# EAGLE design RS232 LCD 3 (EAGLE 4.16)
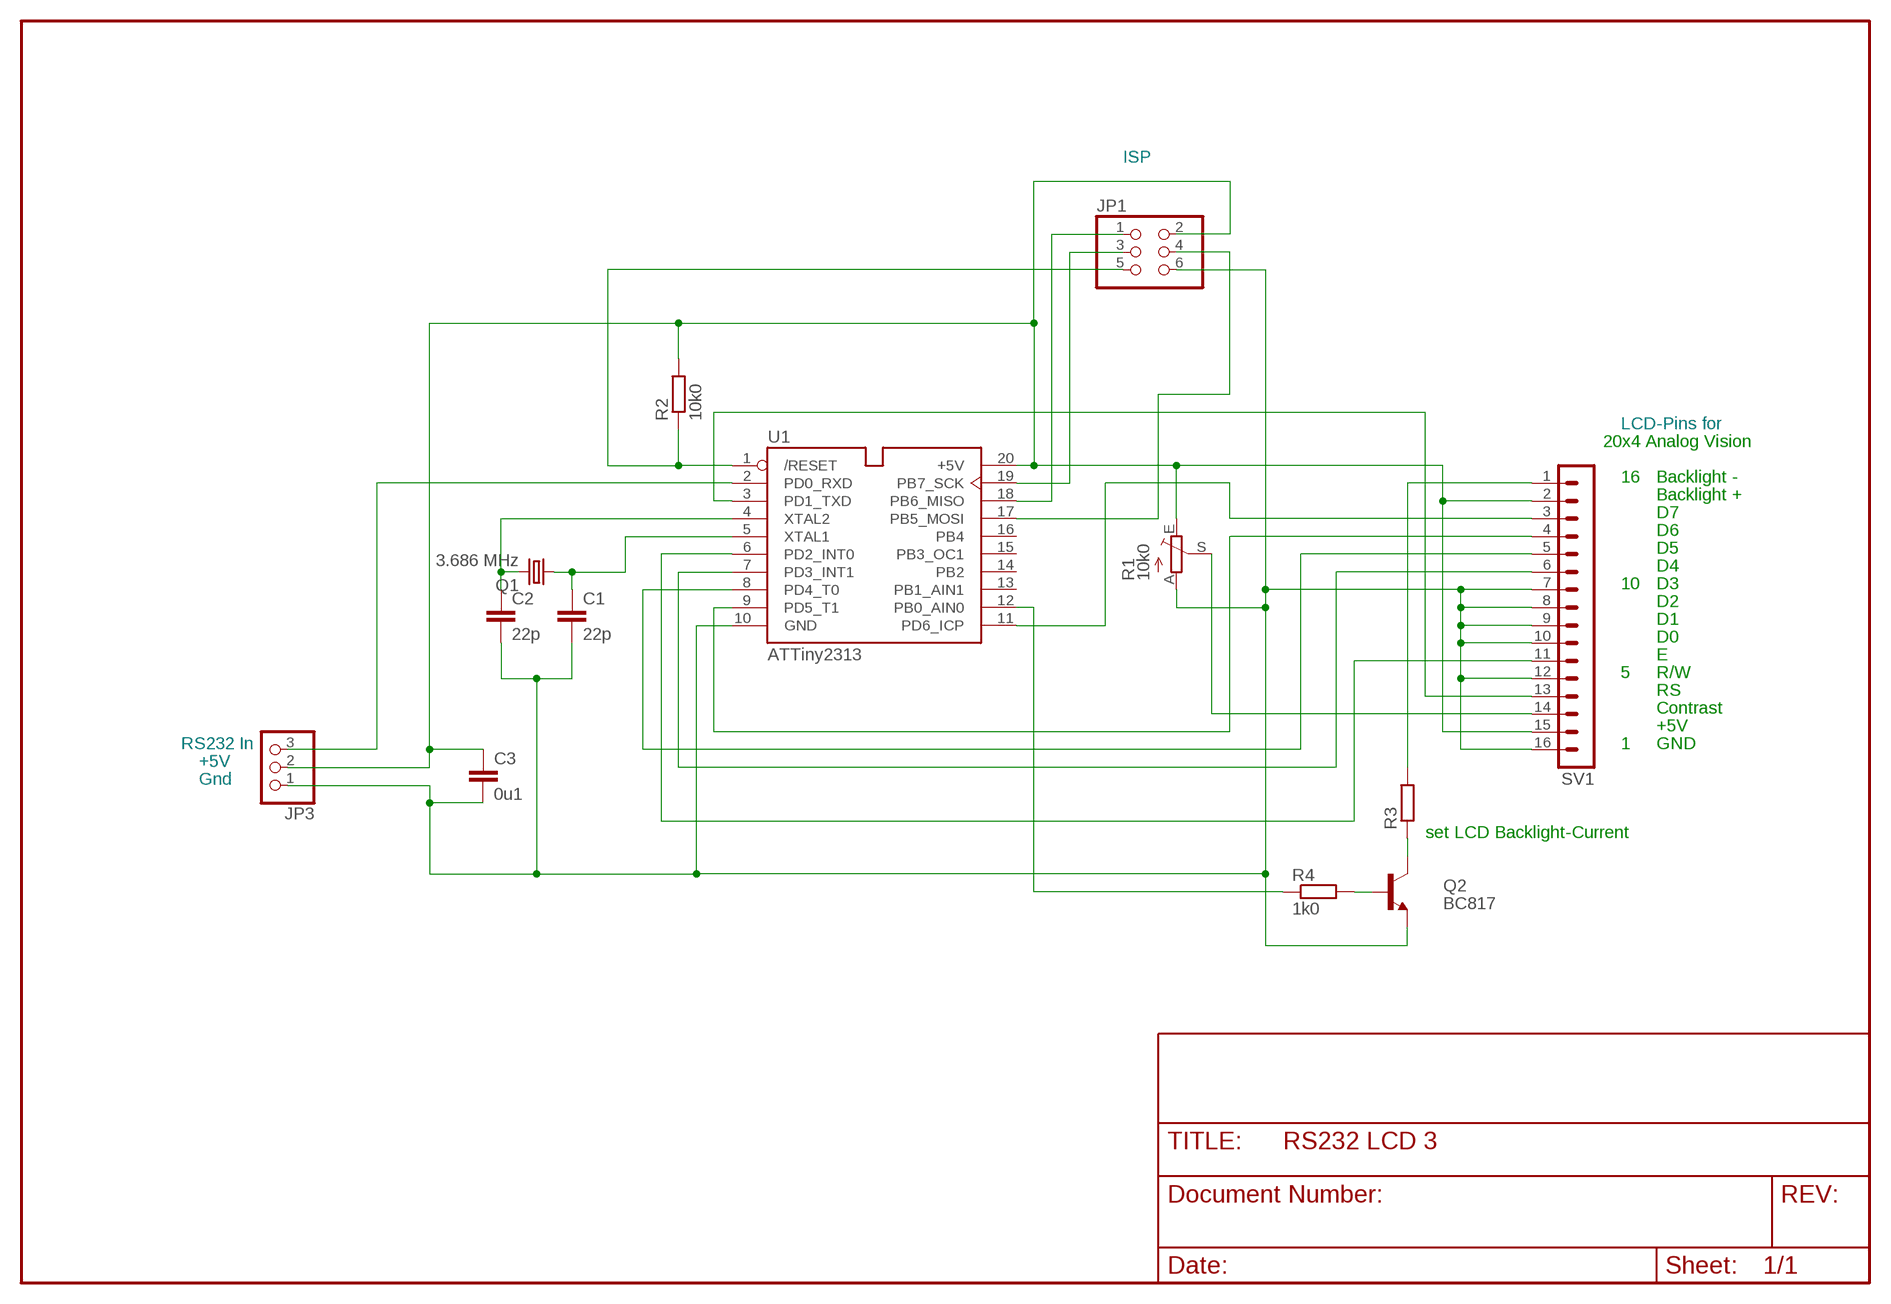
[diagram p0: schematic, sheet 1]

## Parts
C1  22p  C-EU050-025X075  [C050-025X075]
C2  22p  C-EU050-025X075  [C050-025X075]
C3  0u1  C-EU025-030X050  [C025-030X050]
JP1  PINHD-2X3  [2X03]
JP3  PINHD-1X3  [1X03]
Q1  3.686 MHz  CRYSTALHC18U-V  [HC18U-V]
Q2  BC817  BC817-16LT1SMD  [SOT23-BEC]
R1  10k0  TRIM_EU-PT10  [PT-10]
R2  10k0  R-EU_0207/10  [0207/10]
R3  R-EU_0207/10  [0207/10]
R4  1k0  R-EU_0207/10  [0207/10]
SV1  MA16-1  [MA16-1]
U1  ATTiny2313  AT90S2313_SO-20  [SO-20]

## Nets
+5V [Power]: C3.1 JP1.2 JP3.2 R1.E R2.2 SV1.2 SV1.15 U1.20(+5V)
BL- [Power]: R3.2 SV1.1
BL_BASE: Q2.B R4.2
BL_COLLECTOR [Power]: Q2.C R3.1
BL_CONTROL: R4.1 U1.12(PB0_AIN0)
CONTR: R1.S SV1.14
D4: SV1.6 U1.7(PD3_INT1)
D5: SV1.5 U1.8(PD4_T0)
D6: SV1.4 U1.9(PD5_T1)
D7: SV1.3 U1.11(PD6_ICP)
E: SV1.11 U1.6(PD2_INT0)
GND [Power]: C1.2 C2.2 C3.2 JP1.6 JP3.1 Q2.E R1.A SV1.7 SV1.8 SV1.9 SV1.10 SV1.12 SV1.16 U1.10(GND)
MISO: JP1.1 U1.18(PB6_MISO)
MOSI: JP1.4 U1.17(PB5_MOSI)
R/S: SV1.13 U1.3(PD1_TXD)
RST: JP1.5 R2.1 U1.1(/RESET)
RXD: JP3.3 U1.2(PD0_RXD)
SCK: JP1.3 U1.19(PB7_SCK)
XTAL1: C1.1 Q1.1 U1.5(XTAL1)
XTAL2: C2.1 Q1.2 U1.4(XTAL2)
Unconnected: U1.13(PB1_AIN1) U1.14(PB2) U1.15(PB3_OC1) U1.16(PB4)

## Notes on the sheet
- ISP
- LCD-Pins for
- 20x4 Analog Vision
- 16 | Backlight -
- Backlight +
- D7
- D6
- D5
- D4
- 10 | D3
- D2
- D1
- D0
- E
- 5 | R/W
- RS
- Contrast
- +5V
- RS232 In | 1 | GND
- +5V
- Gnd
- set LCD Backlight-Current

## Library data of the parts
C1-C3 = rcl:C-EU: CAPACITOR, European symbol
JP1 = pinhead:PINHD-2X3: PIN HEADER
JP3 = pinhead:PINHD-1X3: PIN HEADER
Q1 = crystal:CRYSTAL: CRYSTAL
Q2 = transistor-npn:BC817*: NPN Transistor
R1 = pot:TRIM_EU-: POTENTIOMETER
R2-R4 = rcl:R-EU_: RESISTOR, European symbol
SV1 = con-lstb:MA16-1
U1 = atmel_prototype_header:AT90S2313: 8-bit AVR Microcontroller with 2K bytes In-System Programmable Flash

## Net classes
0 default: width 0.254 mm
1 Power: width 0.61 mm

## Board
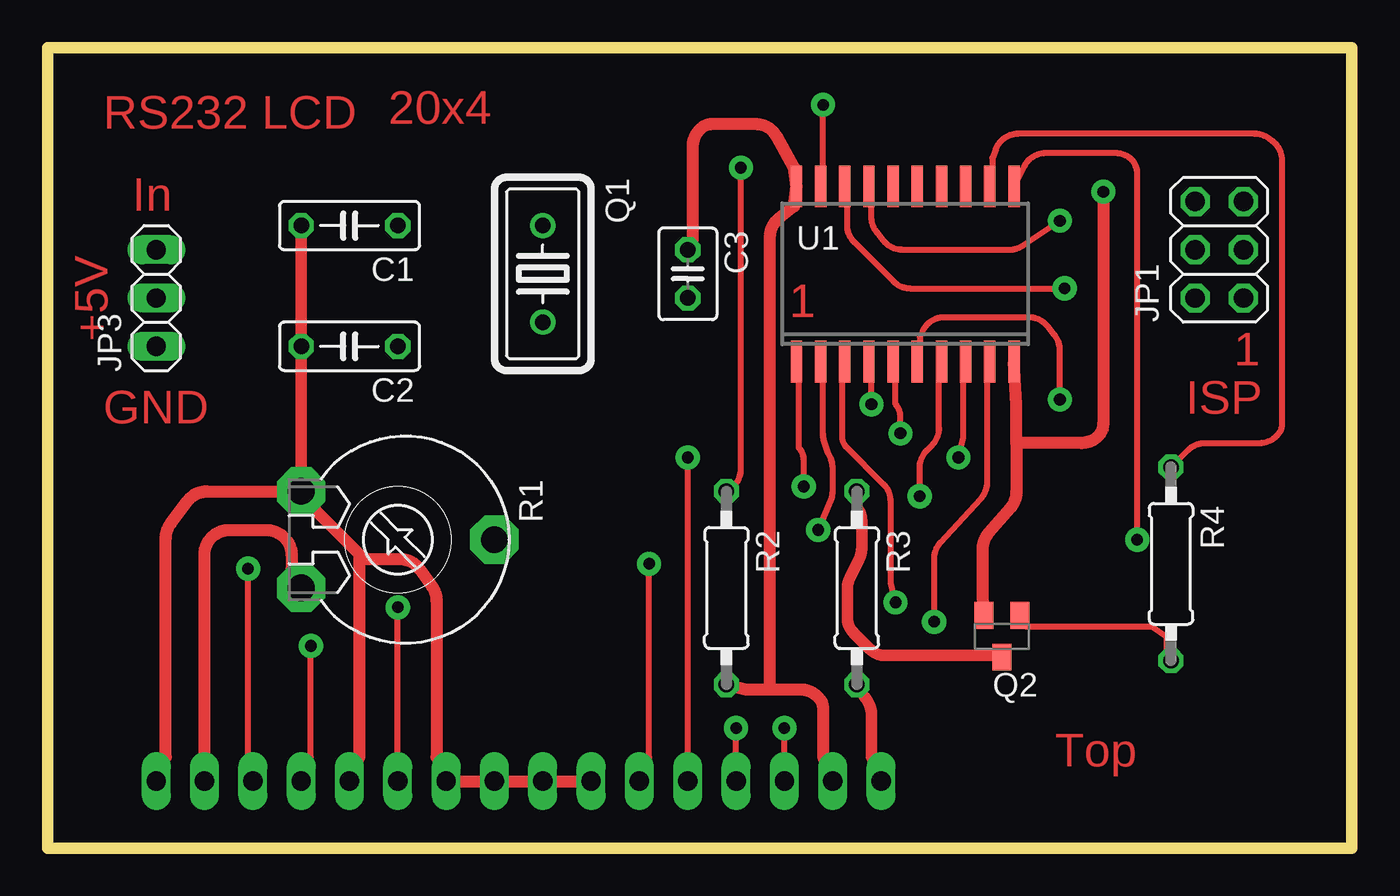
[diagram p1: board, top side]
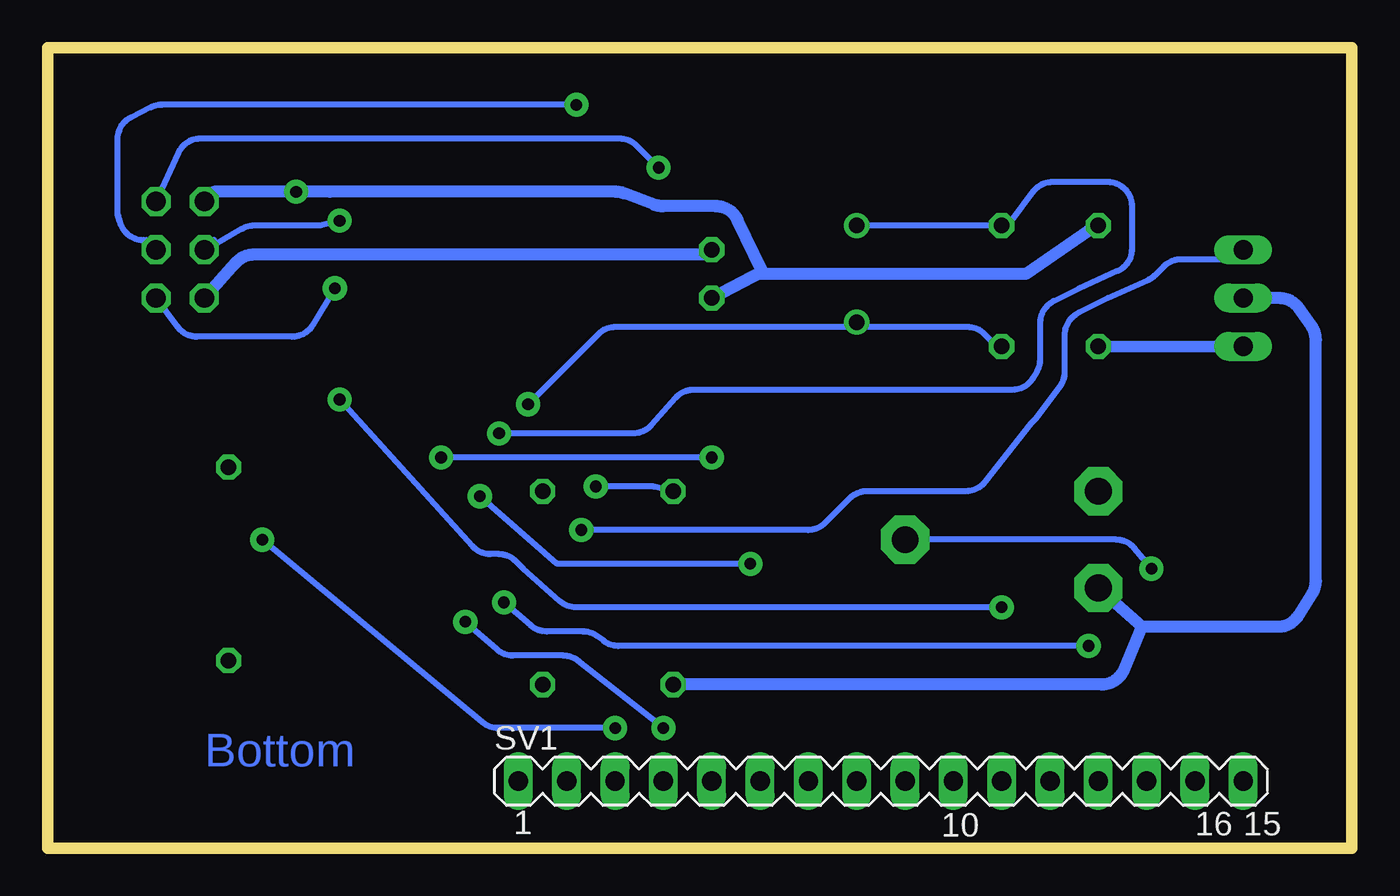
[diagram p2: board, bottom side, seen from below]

Size 68.56 x 42.09 mm. Coordinates in mm from the lower left corner, seen from the top.
Outline: 0,0 68.56,0 68.56,42.09 0,42.09 0,0
Copper layers (1*16): Top 0.035mm / dielectric 1.5mm / Bottom 0.035mm
Design rules "Doppelt_eigene_grosse_vias": minimum track width 12mil, minimum drill 24mil, track to track 15mil, track to pad 15mil, pad to pad 20mil, via to via 20mil, smd to smd 8mil, copper to edge 20mil, drill to drill 8mil, minimum pad ring 10mil, minimum via ring 13mil, stop-mask expansion 4mil, vias tented up to drill 0mil, thermal gap 10mil
tRestrict: area 59.1,27.6 to 64.1,35.3; area 24.8,26.4 to 27.3,34; area 4.4,25.1 to 7,32.7; area 4.4,-0.3 to 43.8,2.2
bRestrict: area 4.4,2.2 to 45.1,4.8
vRestrict: area 38.7,27.6 to 51.4,32.7

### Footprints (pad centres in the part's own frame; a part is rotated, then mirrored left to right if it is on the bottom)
C050-025X075 = drill 0.813 octagon: 1 -2.54,0; 2 2.54,0
C025-030X050 = drill 0.813 octagon: 1 -1.27,0; 2 1.27,0
2X03 = drill 1.016 octagon: 1 -2.54,-1.27; 2 -2.54,1.27; 3 0,-1.27; 4 0,1.27; 5 2.54,-1.27; 6 2.54,1.27
1X03 = drill 1.016 long: 1 -2.54,0; 2 0,0; 3 2.54,0
HC18U-V = drill 0.813 round: 1 -2.54,0; 2 2.54,0
SOT23-BEC = smd 1 x 1.4: B -0.95,-1.1; C 0,1.1; E 0.95,-1.1
PT-10 = drill 1.4 pad 2.54 octagon: A -2.54,-5.08; E 2.54,-5.08; S 0,5.08
0207/10 = drill 0.813 octagon: 1 -5.08,0; 2 5.08,0
MA16-1 = drill 1.016 long: 1 -19.05,0; 2 -16.51,0; 3 -13.97,0; 4 -11.43,0; 5 -8.89,0; 6 -6.35,0; 7 -3.81,0; 8 -1.27,0; 9 1.27,0; 10 3.81,0; 11 6.35,0; 12 8.89,0; 13 11.43,0; 14 13.97,0; 15 16.51,0; 16 19.05,0
SO-20 = smd 0.6 x 2.2: 1 -5.715,-4.6; 2 -4.445,-4.6; 3 -3.175,-4.6; 4 -1.905,-4.6; 5 -0.635,-4.6; 6 0.635,-4.6; 7 1.905,-4.6; 8 3.175,-4.6; 9 4.445,-4.6; 10 5.715,-4.6; 11 5.715,4.6; 12 4.445,4.6; 13 3.175,4.6; 14 1.905,4.6; 15 0.635,4.6; 16 -0.635,4.6; 17 -1.905,4.6; 18 -3.175,4.6; 19 -4.445,4.6; 20 -5.715,4.6

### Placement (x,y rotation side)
C1  15.87,32.73 180 top
C2  15.87,26.38 180 top
C3  33.65,30.19 270 top
JP1  61.59,31.46 90 top
JP3  5.71,28.92 90 top
Q1  26.03,30.19 270 top
Q2  50.16,11.14 180 top
R1  18.41,16.22 270 top
R2  35.68,13.68 270 top
R3  42.54,13.68 270 top
R4  59.05,14.95 270 top
SV1  24.76,3.52 0 bottom
U1  45.08,30.19 0 top

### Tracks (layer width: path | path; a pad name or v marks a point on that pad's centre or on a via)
+5V
  Top 0.635: SV1.15 8.25,15.44 arc-45 8.62,16.34 8.64,16.35 arc-45 9.54,16.73 11.51,16.73 arc-27 12.07,16.59 12.12,16.57 arc-63 12.82,15.43 12.82,14.69 R1.E | 37.97,8.34 39.57,8.34 arc-56 40.63,7.78 arc-34 40.76,7.35 40.76,4.79 SV1.2 | 37.97,8.34 36.7,8.34 R2.2 | C3.1 33.9,31.97 33.9,36.87 arc-56 34.47,37.93 arc-34 34.9,38.06 37.22,38.06 arc-61 38.33,37.41 39.24,35.78 U1.20 39.24,33.74 38.45,33.11 arc51 37.97,32.12 37.97,8.34
  Bottom 0.635: JP3.2 3.82,28.92 arc54 2.79,28.39 2.14,27.47 arc36 1.9,26.73 1.9,14.04 arc32 2.09,13.37 2.8,12.24 arc58 3.87,11.65 11.04,11.65 | JP1.2 58.67,30.78 arc48 57.72,31.2 33.9,31.2 C3.1 | R1.E 11.04,11.65 | 11.04,11.65 11.99,9.38 arc67 13.16,8.6 R2.2
BL-
  Top 0.305: 42.93,7.95 42.79,8.09 R3.2
  Top 0.61: 42.93,7.95 arc-45 43.3,7.06 43.3,4.79 SV1.1
BL_BASE
  Top 0.305: Q2.B 51.43,11.65 58.03,11.65 58.8,11.14 58.8,10.38 R4.2
BL_COLLECTOR
  Top 0.305: 42.66,17.76 42.54,18 | 49.91,10.12 Q2.C
  Top 0.61: 49.91,10.12 44.08,10.12 arc-45 43.18,10.49 42.4,11.27 arc-45 42.03,12.17 42.03,13.63 arc-27 42.17,14.2 42.66,15.19 arc27 42.79,15.76 42.79,17.19 arc27 42.66,17.76 | 42.54,18 R3.1
BL_CONTROL
  Top 0.305: U1.12 49.65,35.78 49.65,36.28 49.84,36.76 arc-68 51.02,37.55 63.45,37.55 arc-37 64.22,37.3 64.38,37.17 arc-53 64.89,36.16 64.89,22.3 arc-34 64.76,21.86 arc-56 63.7,21.3 60.85,21.3 arc45 59.95,20.93 R4.1
CONTR  (via drill 0.61)
  Top 0.305: v10.54,14.69 10.54,5.04 SV1.14
  Bottom 0.305: v10.54,14.69 11.42,15.76 arc-50 12.4,16.22 R1.S
D4  (via drill 0.61)
  Top 0.305: v45.84,18.5 45.84,20.01 arc-45 46.21,20.91 46.49,21.18 arc45 46.86,22.08 46.86,24.6 U1.7 | v31.62,14.95 31.62,4.79 SV1.6
  Bottom 0.305: v45.84,18.5 41.78,14.95 v31.62,14.95
D5  (via drill 0.61)
  Top 0.305: v47.87,20.54 48.13,21.55 48.13,24.6 U1.8 | SV1.5 v33.65,20.54
  Bottom 0.305: v33.65,20.54 v47.87,20.54
D6  (via drill 0.61)
  Top 0.305: v46.6,11.9 46.6,15.22 arc-43 46.94,16.07 49.06,18.39 arc43 49.4,19.25 49.4,24.6 U1.9 | SV1.4 v36.19,6.31
  Bottom 0.305: v46.6,11.9 44.93,10.44 arc-41 44.1,10.12 41.46,10.12 arc38 40.67,9.85 v36.19,6.31
D7  (via drill 0.61)
  Top 0.305: v57.27,16.22 57.27,35.5 arc56 56.83,36.33 arc34 56.12,36.54 52.46,36.54 arc63 51.33,35.84 U1.11 | SV1.3 v38.73,6.31
  Bottom 0.305: v38.73,6.31 44.88,6.31 arc40 45.69,6.61 v57.27,16.22
E  (via drill 0.61)
  Top 0.305: v53.21,23.58 53.21,26.19 arc39 52.93,26.98 52.57,27.43 arc51 51.58,27.9 47.13,27.9 arc63 46,27.2 45.84,26.89 45.84,26.63 U1.6 | SV1.11 v18.41,12.66
  Bottom 0.305: v53.21,23.58 46.22,15.87 arc-48 45.28,15.46 44.84,15.46 arc45 43.95,15.08 43.56,14.69 41.63,12.98 arc-42 40.79,12.66 v18.41,12.66
GND  (via drill 0.61)
  Top 0.61: C1.2 C2.2 R1.A
  Top 0.635: SV1.7 SV1.8 SV1.9 SV1.10 20.44,4.79 20.44,13.02 arc36 20.21,13.76 19.55,14.67 arc54 18.52,15.2 16.38,15.2 | SV1.16 6.22,4.79 6.22,16.3 arc-37 6.47,17.07 7.36,18.25 arc-53 8.38,18.76 R1.A 14.09,17.74 16.38,15.46 16.38,15.2 | 16.38,15.2 16.38,4.79 SV1.12 | 50.92,21.3 50.92,23.33 U1.10 | 50.92,21.3 50.92,18.73 arc-41 50.61,17.89 49.46,16.58 arc41 49.14,15.74 49.14,13.17 Q2.E | v55.49,34.51 55.49,22.34 arc-56 55.05,21.51 arc-34 54.35,21.3 50.92,21.3
  Bottom 0.61: C2.2 JP3.1
  Bottom 0.635: 30.98,30.32 31.11,30.19 17.14,30.19 13.84,32.47 C1.2 | 30.98,30.32 33.14,29.17 C3.2 | 53.72,34.51 59.81,34.51 JP1.6 | 30.98,30.32 32.29,33.02 arc-64 33.43,33.74 36.21,33.74 arc21 36.66,33.83 38.26,34.43 arc-21 38.71,34.51 53.72,34.51 | 53.72,34.51 v55.49,34.51
MISO  (via drill 0.61)
  Top 0.305: v53.46,29.43 45.35,29.43 arc-45 44.45,29.8 42.4,31.85 arc-45 42.03,32.75 42.03,33.74 U1.18
  Bottom 0.305: v53.46,29.43 54.62,27.5 arc59 55.71,26.89 60.7,26.89 arc53 61.72,27.39 JP1.1
MOSI  (via drill 0.61)
  Top 0.305: v53.21,32.98 51.24,31.67 arc-34 50.54,31.46 44.93,31.46 arc-51 43.94,31.94 43.58,32.38 arc-39 43.3,33.17 43.3,33.74 U1.17
  Bottom 0.305: v53.21,32.98 54.22,32.73 57.7,32.73 arc-30 58.33,32.56 59.81,31.71 59.81,31.97 JP1.4
R/S  (via drill 0.61)
  Top 0.305: v44.57,12.92 44.32,13.93 44.32,18.23 arc45 43.95,19.13 41.96,21.11 arc-45 41.78,21.56 41.78,24.6 U1.3 | v13.84,10.63 13.84,4.79 SV1.13
  Bottom 0.305: v13.84,10.63 38.56,10.63 arc37 39.32,10.88 39.66,11.14 arc-37 40.42,11.39 42.32,11.39 arc41 43.15,11.7 v44.57,12.92
RST  (via drill 0.61)
  Top 0.305: v39.75,19.01 39.75,20.43 arc45 39.49,21.04 39.49,24.6 U1.1 | R2.1 35.88,18.89 arc56 36.44,19.95 v36.44,35.78
  Bottom 0.305: v39.75,19.01 36.7,19.01 R2.1 | v36.44,35.78 37.6,36.93 arc-45 38.49,37.3 60.52,37.3 arc-65 61.68,36.56 JP1.5
RXD  (via drill 0.61)
  Top 0.305: v40.51,16.73 41.17,18.26 arc23 41.27,18.77 41.27,19.98 arc27 41.14,20.55 41.02,20.79 40.83,21.36 arc-18 40.76,21.76 40.76,24.6 U1.2
  Bottom 0.305: JP3.3 6.98,30.95 8.99,30.95 arc-45 9.89,30.58 10.37,30.1 arc21 10.75,29.84 12.82,28.92 14.35,28.16 14.54,28.03 arc-56 15.11,26.97 15.11,25.02 arc37 15.36,24.26 16.63,22.57 16.89,22.31 19.3,19.24 arc52 20.3,18.76 25.5,18.76 arc-45 26.4,18.39 27.69,17.1 arc45 28.59,16.73 v40.51,16.73
SCK  (via drill 0.61)
  Top 0.305: v40.76,39.08 40.76,35.78 U1.19
  Bottom 0.305: v40.76,39.08 62.56,39.08 arc-27 63.13,38.94 64.19,38.41 arc-63 64.89,37.28 64.89,33.48 arc-22 64.8,33.01 64.7,32.76 arc-68 63.52,31.97 63.37,31.97 JP1.3
XTAL1  (via drill 0.61)
  Top 0.305: v44.83,21.81 44.83,22.72 arc45 44.57,23.33 44.57,24.6 U1.5
  Bottom 0.305: v44.83,21.81 37.78,21.81 arc-48 36.83,22.23 35.55,23.67 arc48 34.6,24.09 17.86,24.09 arc-59 16.77,24.71 16.56,25.06 arc-31 16.38,25.71 16.38,27.62 arc63 15.68,28.76 14.35,29.43 12.3,30.36 arc-66 11.55,31.51 11.55,33.74 arc-90 12.82,35.01 15.74,35.01 arc-53 16.76,34.51 17.9,32.98 C1.1 Q1.1
XTAL2  (via drill 0.61)
  Top 0.305: v43.3,23.33 43.3,24.6 U1.4
  Bottom 0.305: v43.3,23.33 39.61,27.02 arc45 38.71,27.39 26.54,27.39 Q1.2 25.52,27.39 20.21,27.39 arc45 19.31,27.02 18.92,26.63 C2.1

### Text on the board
Top: RS232 LCD | 20x4 | In | 1 | +5V | 1 | ISP | GND | Top
Bottom: Bottom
